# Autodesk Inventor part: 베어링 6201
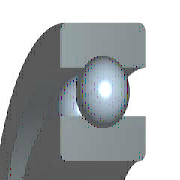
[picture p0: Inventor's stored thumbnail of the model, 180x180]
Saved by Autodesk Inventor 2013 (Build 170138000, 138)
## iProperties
Created: 2015-12
Part Number: 베어링 6201
Material: 강철, 연강
Description: 깊은 그루브 볼 베어링
Document SubType Name: Modeling
Standard: KS B 2023
Designer: mdu
Standards Organization: KS
Language: ko-KR
Size Designation: 6201 - 12 x 32 x 10
Categories: <MemberInstance><Categories><Category DisplayName="샤프트 부품" InternalName="7f7aeb1f-a693-4053-b835-cee3144e0d98" Mnemonic="SHFT"><Category DisplayName="베어링" Inter
Density: 7.86 g/cm^3
Mass: 36.8026 g
Surface Area: 42.5728 cm^2
Volume: 4.68226 cm^3
Company: 한국ATC센터
IsCustomPart: 1
Author: mdu
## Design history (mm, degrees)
sketch "스케치" dims "d0" = 5.2 (= -0.26 x WD + 0.26 x BD)
  geometry: L1 (2.4, 11)-(7.6, 11); L2 (5, 11)-(5, 8.4); L3 (5, 11)-(5, 13.6); L4 (3.068, 9.26)-(0, 9.26); L5 (0, 6)-(10, 6); L6 (3.068, 12.74)-(0, 12.74); L7 (0, 16)-(10, 16); L8 (10, 6)-(10, 9.26); L9 (6.932, 9.26)-(10, 9.26); L10 (6.932, 12.74)-(10, 12.74); L11 (10, 16)-(10, 12.74); L12 (-1.4, 0)-(8.4, 0) reference; L13 (0, -0.3)-(0, 5.3) reference
  constraints: 22 end point, 4 point on line, 2 collinear, 2 perpendicular, 2 symmetric about line, 1 midpoint, 1 parallel, 14 other
  dimensions: "d9" = 12 diameter of L5 L12 (= WD); "d11" = 32 diameter of L7 L12 (= BD); "d12" = 10 distance between parallel lines of L8 L13 (= KB); "d13" = 18.52 diameter of L9 L12 (= 0.326 x BD + 0.674 x WD)
revolve "본체" stored, may be unused: angle "d6" = 90 deg
revolve "볼" stored, may be unused: angle "d7" = 90 deg
pattern_circular "IDS_ARRAYBALL[SIMPL:T]" dims angle "d3" = 360 deg
body "Solid1"
fillet "모깎기1" dims "d1" = 0.6 (= KRS)
other parameters: "WD" = 12 [user parameter; used in 5 equation terms], "BD" = 32 [user parameter; used in 5 equation terms], "KB" = 10 [user parameter; used in 1 equation term], "KRS" = 0.6 [user parameter; used in 1 equation term], "d4" = 0, "d5" = 0, "d8" = 0, "d14" = 0, "d15" = 0, "BBA" = 0 [user parameter], "BC0" = 3100000 [user parameter], "BC" = 6890000 [user parameter], "BR" = 16 (= 0.5 x BD) [user parameter], "WR" = 6 (= 0.5 x WD) [user parameter]
